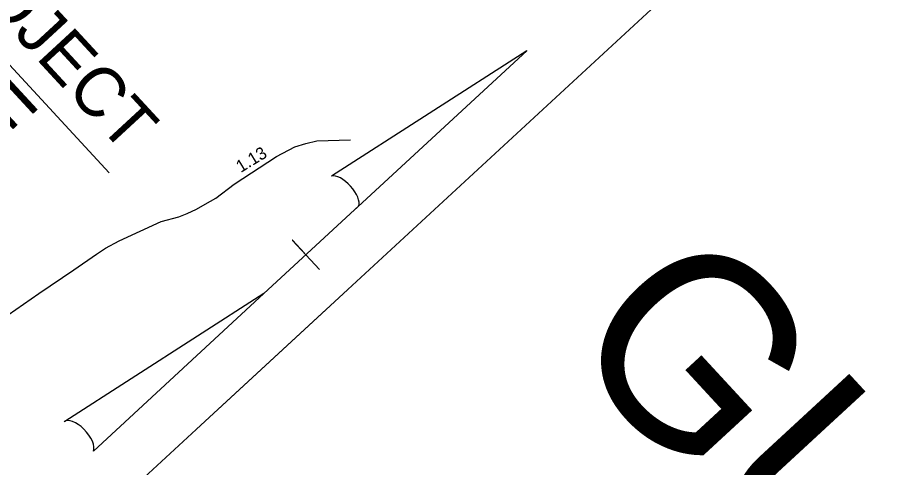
# Model space of a CAD drawing. Extents: x 1695041 to 1706254, y 786537 to 798223.
# Drawn here: x 1703431.2 to 1703837.1, y 796570.2 to 796781.2 of the extents above; entities that cross this region are included whole.
import ezdxf

# ---------------------------------------------------------------- set-up
doc = ezdxf.new("R2010")
doc.units = 0
for name, color, linetype in [('Default', 7, 'Continuous'), ('Old_Level_1', 7, 'Continuous'), ('Old_Level_2', 7, 'Continuous'), ('Old_Level_32', 7, 'Continuous'), ('Prop North Arrow for Plan Sheets CELL', 7, 'Continuous'), ('Sheet Data Field CELL', 7, 'Continuous')]:
    doc.layers.add(name, color=color, linetype=linetype)

msp = doc.modelspace()

# ---------------------------------------------------------------- linework, layer by layer
at = {"layer": 'Default'}
msp.add_lwpolyline([(1703207.65, 797564.73), (1702636.99, 797037.98), (1703265.12, 796357.5), (1703835.77, 796884.26)], dxfattribs=at)
at = {"layer": 'Old_Level_1'}
msp.add_line((1703362.1, 796829.74), (1703474.22, 796708.27), dxfattribs=at)
at = {"layer": 'Old_Level_32'}
msp.add_lwpolyline([(1703393.61, 796619.66), (1703412.04, 796631.82), (1703426.87, 796641.71), (1703441.25, 796651.77), (1703457.65, 796662.81), (1703468.28, 796670.28), (1703472.5, 796673.05), (1703478.97, 796676.5), (1703498.59, 796685.51), (1703506.83, 796687.71), (1703510.78, 796689.24), (1703515.17, 796691.26), (1703519.2, 796693.57), (1703524.18, 796696.51), (1703532.81, 796702.93), (1703552.59, 796715.99), (1703561.22, 796720.54), (1703566.39, 796722.11), (1703571.54, 796723.26), (1703587.36, 796723.78)], dxfattribs=at)
at = {"layer": 'Prop North Arrow for Plan Sheets CELL'}
for p, q in [((1703578.33, 796706.86), (1703669.85, 796765.57)), ((1703669.93, 796765.48), (1703588.79, 796690.59)), ((1703669.93, 796765.48), (1703669.85, 796765.57)), ((1703669.93, 796765.48), (1703669.85, 796765.57)), ((1703546.7, 796651.73), (1703591.17, 796692.78)), ((1703588.79, 796690.59), (1703591.08, 796692.7)), ((1703560.12, 796676.69), (1703560.04, 796676.78)), ((1703565.68, 796670.67), (1703560.12, 796676.69)), ((1703560.2, 796676.61), (1703572.73, 796663.03)), ((1703546.7, 796651.73), (1703453.41, 796591.87)), ((1703466.91, 796577.93), (1703546.7, 796651.73))]:
    msp.add_line(p, q, dxfattribs=at)
for centre, start_param, end_param in [((1703583.97, 796699.06), 0.216388, 2.908219), ((1703459.77, 796584.42), 0.201328, 3.141593)]:
    msp.add_ellipse(centre, major_axis=(6.58, -7.23), ratio=0.461098, start_param=start_param, end_param=end_param, dxfattribs=at)

# ---------------------------------------------------------------- texts
at = {"layer": 'Default'}
msp.add_text('1.13', height=5.775, rotation=31.3388, dxfattribs=at).set_placement((1703535.89, 796708.21))
at = {"layer": 'Old_Level_2'}
for s, height, p in [('PROJECT ', 23.173, (1703383.41, 796822.91)), ('SITE', 27.263, (1703367.32, 796777.31))]:
    msp.add_text(s, height=height, rotation=312.7091, dxfattribs=at).set_placement(p)
at = {"layer": 'Sheet Data Field CELL'}
msp.add_text('       GUILFORD COUNTY       ', height=90, rotation=312.7091, dxfattribs=at).set_placement((1703526.25, 796800.69))

doc.saveas('drawing.dxf')
